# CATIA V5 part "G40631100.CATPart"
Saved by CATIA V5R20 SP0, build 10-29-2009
Part number: G40631100
Revision: 3
Definition: design
Nomenclature: G40631100
Source: made
Description: NOT SPECIFIED
Bounding box of the stored display mesh (mm): x -50 to 50, y -12.5 to 12.5, z -31 to 0
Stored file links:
  C:\Users\Raffaele\Desktop\3D X SITO CF\BOLEX\30-GUIDE STRIP REF 406\G40631100.CATPart
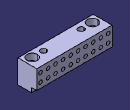
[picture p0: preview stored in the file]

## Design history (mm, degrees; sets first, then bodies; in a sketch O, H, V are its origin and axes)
Body1 "MANIFOLD_SOLID_BREP #3688" (main body)
  Solid1: solid without history
Body2 "MANIFOLD_SOLID_BREP #3826"
  Solid2: solid without history
Body3 "MANIFOLD_SOLID_BREP #3964"
  Solid3: solid without history
Body4 "MANIFOLD_SOLID_BREP #4102"
  Solid4: solid without history
Body5 "MANIFOLD_SOLID_BREP #4240"
  Solid5: solid without history
Body6 "MANIFOLD_SOLID_BREP #4378"
  Solid6: solid without history
Body7 "MANIFOLD_SOLID_BREP #4490"
  Solid7: solid without history
Body8 "MANIFOLD_SOLID_BREP #4602"
  Solid8: solid without history
Body9 "MANIFOLD_SOLID_BREP #4714"
  Solid9: solid without history
Body10 "MANIFOLD_SOLID_BREP #4826"
  Solid10: solid without history
Body11 "MANIFOLD_SOLID_BREP #4938"
  Solid11: solid without history
Body12 "MANIFOLD_SOLID_BREP #5050"
  Solid12: solid without history
Body13 "MANIFOLD_SOLID_BREP #5188"
  Solid13: solid without history
Body14 "MANIFOLD_SOLID_BREP #5326"
  Solid14: solid without history
Body15 "MANIFOLD_SOLID_BREP #5438"
  Solid15: solid without history
Body16 "MANIFOLD_SOLID_BREP #5550"
  Solid16: solid without history
Body17 "MANIFOLD_SOLID_BREP #5662"
  Solid17: solid without history
Body18 "MANIFOLD_SOLID_BREP #5774"
  Solid18: solid without history
Body19 "MANIFOLD_SOLID_BREP #5886"
  Solid19: solid without history
Body20 "MANIFOLD_SOLID_BREP #5998"
  Solid20: solid without history
Body21 "MANIFOLD_SOLID_BREP #6110"
  Solid21: solid without history
Body22 "MANIFOLD_SOLID_BREP #6222"
  Solid22: solid without history
Body23 "MANIFOLD_SOLID_BREP #6334"
  Solid23: solid without history
Body24 "MANIFOLD_SOLID_BREP #6446"
  Solid24: solid without history
Body25 "MANIFOLD_SOLID_BREP #6584"
  Solid25: solid without history
Body26 "MANIFOLD_SOLID_BREP #6722"
  Solid26: solid without history
Body27 "MANIFOLD_SOLID_BREP #6834"
  Solid27: solid without history
Body28 "MANIFOLD_SOLID_BREP #6946"
  Solid28: solid without history
Body29 "MANIFOLD_SOLID_BREP #7058"
  Solid29: solid without history
Body30 "MANIFOLD_SOLID_BREP #7170"
  Solid30: solid without history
